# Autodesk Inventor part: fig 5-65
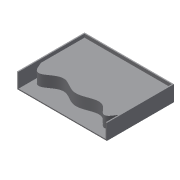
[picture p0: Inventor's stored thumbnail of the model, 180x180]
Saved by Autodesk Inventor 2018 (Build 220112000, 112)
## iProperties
Created: 2004-05
Part Number: fig 5-65
Document SubType Name: Modeling
Designer: CADCIM Technologies
Manufacturer: Standard
Standards Organization: Custom
Density: 1 g/cm^3
Material: Generic
Appearance: Default
Author: CADCIM Technologies
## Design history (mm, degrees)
sketch "Sketch1"
  geometry: L1 (-40, -30)-(40, -30); L2 (40, -30)-(40, 30); L3 (40, 30)-(-40, 30); L4 (-40, 30)-(-40, -30); 1 further point
  constraints: 8 end point, 2 parallel, 1 horizontal, 1 perpendicular, 1 other
  dimensions: "d0" = 80 distance of L1.start L1.end; "d1" = 60 distance of L3.end L1.start; "d2" = 30 distance from line of point (0, 0) L1; "d3" = 40 distance from line of point (0, 0) L4
extrude "Extrusion1" new body sketch "Sketch1" distance "d4" = 14; taper "d5" = 0 deg
shell "Shell1" dims "d6" = 1
workplane "Work Plane1"
sketch "Sketch2"
  geometry: L1 (78, -13)-(78, -11.813); L2 (0, -11.813)-(0, -13); L3 (0, -13)-(78, -13); L4 (0, -11.813)-(17.826, -3.295); L5 (17.826, -3.295)-(60.174, -3.295); L6 (60.174, -3.295)-(78, -11.813); L7 (79, -13.795)-(78, -13.795); L8 (78, 0)-(78, -13) reference; L9 (0, -13)-(0, 0) reference; L10 (78, -13)-(0, -13) reference
  constraints: 14 end point, 3 collinear, 2 equal length, 2 vertical, 1 horizontal alignment, 1 parallel, 1 point on line
extrude "Extrusion2" join sketch "Sketch2" stored distance "d8" = 14; taper "d9" = 0 deg
workplane "Work Plane2"
sketch "Sketch4"
  geometry: 7 further points
  constraints: 7 other
extrude "Extrusion9" join sketch "Sketch4" distance "d35" = 10; taper "d36" = 0 deg
body "Solid1"
other parameters: "d7" = 23, "d18" = 4
